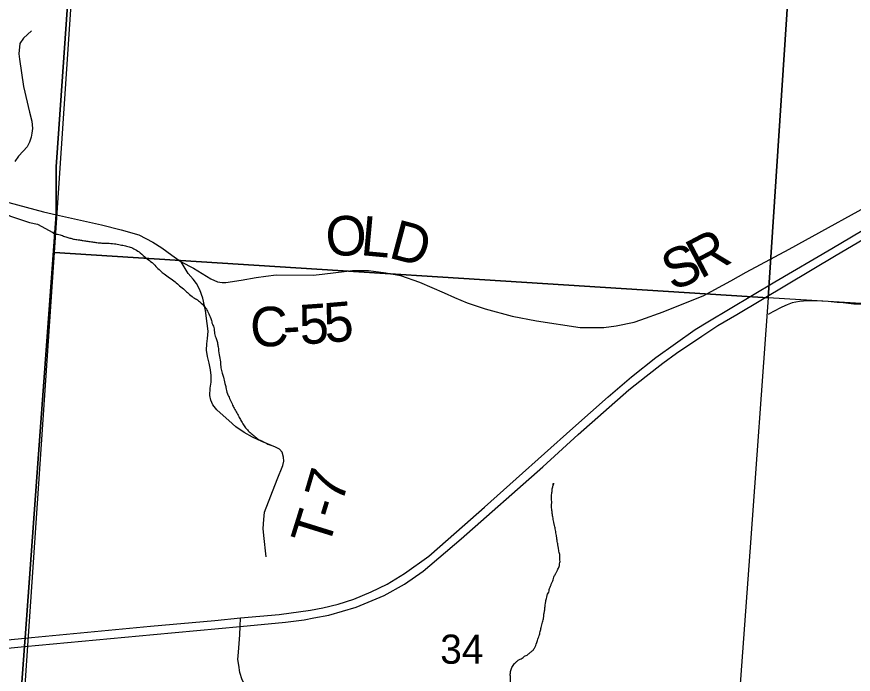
# Model space of a CAD drawing. Extents: x -13.7 to 34, y 0 to 32.3.
# Drawn here: x 25.84 to 27.041, y 18.512 to 19.456 of the extents above; entities that cross this region are included whole.
import ezdxf

# ---------------------------------------------------------------- set-up
doc = ezdxf.new("R2010")
doc.units = 0
for name, color, linetype in [('GM_X_Corporation', 7, 'Continuous'), ('GM_X_County_Road', 7, 'Continuous'), ('GM_X_County_Road_Text', 7, 'Continuous'), ('GM_X_Minor_River', 7, 'Continuous'), ('GM_X_Section_Text', 7, 'Continuous'), ('GM_X_State_Route', 7, 'Continuous'), ('GM_X_Township_Road', 7, 'Continuous'), ('GM_X_Township_Road_Text', 7, 'Continuous')]:
    doc.layers.add(name, color=color, linetype=linetype)

msp = doc.modelspace()

# ---------------------------------------------------------------- linework, layer by layer
at = {"layer": 'GM_X_Corporation'}
for points in [[(25.8396, 18.3951), (25.8512, 18.5523), (25.8521, 18.5644), (25.8715, 18.8281), (25.8969, 19.1723), (25.8969, 19.2407), (25.917, 19.5276), (25.9325, 19.8164), (25.9462, 20.0191), (25.9566, 20.1753), (25.9834, 20.5724), (26.0026, 20.9), (23.5167, 20.9)], [(25.8396, 18.3951), (25.8512, 18.5523), (25.8521, 18.5644), (25.8715, 18.8281), (25.8969, 19.1723), (25.8969, 19.2407), (25.917, 19.5276), (25.9325, 19.8164), (25.9462, 20.0191), (25.9566, 20.1753), (25.9834, 20.5724), (26.0026, 20.9), (23.5167, 20.9)], [(29.9598, 20.9), (26.0026, 20.9), (25.9834, 20.5724), (25.9566, 20.1753), (25.9462, 20.0191), (25.9325, 19.8164), (25.917, 19.5276), (25.8969, 19.2407), (25.8969, 19.1723), (25.8715, 18.8281), (25.8521, 18.5644), (25.8512, 18.5523), (25.8396, 18.3951), (25.8286, 18.2247), (25.8036, 17.8534), (25.7648, 17.1991), (25.7595, 17.1252), (25.7591, 17.1039), (25.7561, 17.0683), (25.752, 17.037), (25.7481, 16.9763), (25.7164, 16.6052), (25.6857, 16.1459), (25.6733, 15.948)], [(29.9598, 20.9), (26.0026, 20.9), (25.9834, 20.5724), (25.9566, 20.1753), (25.9462, 20.0191), (25.9325, 19.8164), (25.917, 19.5276), (25.8969, 19.2407), (25.8969, 19.1723), (25.8715, 18.8281), (25.8521, 18.5644), (25.8512, 18.5523), (25.8396, 18.3951), (25.8286, 18.2247), (25.8036, 17.8534), (25.7648, 17.1991), (25.7595, 17.1252), (25.7591, 17.1039), (25.7561, 17.0683), (25.752, 17.037), (25.7481, 16.9763), (25.7164, 16.6052), (25.6857, 16.1459), (25.6733, 15.948)]]:
    msp.add_lwpolyline(points, dxfattribs=at)
for points in [[(26.9853, 20.0635), (26.9188, 19.0522), (25.8944, 19.1175), (25.9617, 20.1223)], [(28.0076, 20.0028), (27.9343, 18.9903), (27.9295, 18.9907), (26.9188, 19.0522), (26.9853, 20.0635)], [(25.8944, 19.1175), (26.9188, 19.0522), (26.8924, 18.6876), (26.8578, 18.216), (26.8422, 18.014), (25.8244, 18.0867)]]:
    msp.add_lwpolyline(points, close=True, dxfattribs=at)
at = {"layer": 'GM_X_County_Road'}
for points in [[(26.7689, 19.0326), (26.8253, 19.0552), (26.8652, 19.0766), (26.8873, 19.0892), (26.9488, 19.1225), (27.0948, 19.2028), (27.131, 19.2223), (27.154, 19.2361), (27.1734, 19.251), (27.1897, 19.2652), (27.2083, 19.2853), (27.2189, 19.2978)], [(25.5601, 19.2293), (25.5694, 19.2351), (25.5787, 19.241), (25.588, 19.2455), (25.5949, 19.2484), (25.6041, 19.2507), (25.6133, 19.2529), (25.6204, 19.2536), (25.6267, 19.2533), (25.6352, 19.2529), (25.6443, 19.2506), (25.6601, 19.2469), (25.6874, 19.2366), (25.7171, 19.2254), (25.7512, 19.2127), (25.7646, 19.2078), (25.7783, 19.2026), (25.8785, 19.1759), (25.8971, 19.1718)], [(25.8971, 19.1718), (25.9616, 19.1573), (25.9898, 19.1502), (26.0152, 19.1427), (26.0353, 19.1324), (26.0482, 19.1244), (26.0628, 19.1137), (26.0762, 19.1042), (26.0938, 19.0949), (26.1187, 19.0799), (26.1285, 19.0755), (26.1348, 19.0744), (26.1403, 19.0743), (26.1625, 19.0777), (26.184, 19.0814), (26.1978, 19.0837), (26.2126, 19.0854), (26.2657, 19.0849), (26.2788, 19.0863), (26.2984, 19.0888), (26.3221, 19.0917), (26.3451, 19.0917), (26.3701, 19.0884), (26.3911, 19.0843), (26.4184, 19.0748), (26.4537, 19.0597), (26.4683, 19.0527), (26.4868, 19.0452), (26.5124, 19.0368), (26.5514, 19.0262), (26.5863, 19.0192), (26.6487, 19.0099), (26.6644, 19.0097), (26.6828, 19.0099), (26.7006, 19.0122), (26.7266, 19.0176), (26.7361, 19.0209), (26.7679, 19.0322), (26.7689, 19.0326)]]:
    msp.add_lwpolyline(points, dxfattribs=at)
at = {"layer": 'GM_X_Minor_River'}
msp.add_lwpolyline([(25.7155, 19.1142), (25.7257, 19.1244), (25.7386, 19.1282), (25.7488, 19.1369), (25.7548, 19.1483), (25.762, 19.1623), (25.7737, 19.1752), (25.7851, 19.1787), (25.8059, 19.1787), (25.8184, 19.1757), (25.8313, 19.1696), (25.8453, 19.1651), (25.8582, 19.1606), (25.87, 19.1583), (25.8921, 19.1463)], dxfattribs=at)
for points in [[(25.8921, 19.1471), (25.8921, 19.1463), (25.8988, 19.1438), (25.9056, 19.1417), (25.912, 19.1396), (25.9176, 19.1379), (25.9232, 19.1366), (25.93, 19.1356), (25.9357, 19.1346), (25.9421, 19.1336), (25.9489, 19.1327), (25.9553, 19.1317), (25.9625, 19.1311), (25.9701, 19.1308), (25.9803, 19.1301), (25.9887, 19.1287), (25.9962, 19.1269), (26.003, 19.1252), (26.0101, 19.1219), (26.0175, 19.1171), (26.026, 19.1096), (26.0323, 19.1048), (26.04, 19.0974), (26.0459, 19.0915), (26.0518, 19.0867), (26.0596, 19.0811), (26.0674, 19.0752), (26.074, 19.0696), (26.081, 19.0637), (26.0865, 19.0586), (26.0936, 19.053), (26.0995, 19.0494), (26.1051, 19.0447), (26.1113, 19.038), (26.1149, 19.0314), (26.1188, 19.0229), (26.1204, 19.0164), (26.1229, 19.0099), (26.1241, 19.0011), (26.1265, 18.9938), (26.1282, 18.9881), (26.1292, 18.9819), (26.1307, 18.9705), (26.1326, 18.9606), (26.1331, 18.9518), (26.1351, 18.9441), (26.1368, 18.9384), (26.1388, 18.9296), (26.1405, 18.9238), (26.1425, 18.9146), (26.1457, 18.9081), (26.1492, 18.9), (26.1521, 18.8938), (26.156, 18.8872), (26.1596, 18.8806), (26.1628, 18.8748), (26.1664, 18.8686), (26.1712, 18.8628), (26.1767, 18.8577), (26.1822, 18.8529), (26.1881, 18.8486), (26.1945, 18.8457), (26.2008, 18.8424), (26.2065, 18.8403)], [(26.541, 18.3977), (26.5415, 18.3999), (26.5427, 18.4022), (26.5451, 18.4044), (26.5467, 18.4085), (26.5479, 18.4107), (26.5484, 18.4142), (26.5487, 18.4221), (26.5484, 18.4248), (26.549, 18.4441), (26.5495, 18.4464), (26.5501, 18.4525), (26.5505, 18.4547), (26.551, 18.4578), (26.5516, 18.465), (26.5526, 18.4706), (26.5527, 18.4756), (26.5524, 18.4782), (26.5518, 18.482), (26.5516, 18.4862), (26.551, 18.4912), (26.55, 18.4969), (26.5493, 18.4992), (26.5488, 18.5046), (26.5489, 18.5076), (26.5486, 18.5106), (26.5487, 18.5133), (26.5491, 18.5159), (26.55, 18.5186), (26.5508, 18.5216), (26.5528, 18.5246), (26.5548, 18.5272), (26.5576, 18.5301), (26.5611, 18.5327), (26.5642, 18.5341), (26.5669, 18.5359), (26.57, 18.5384), (26.5727, 18.5395), (26.5766, 18.5428), (26.5801, 18.5453), (26.5833, 18.5494), (26.5866, 18.5573), (26.5878, 18.5603), (26.5899, 18.5674), (26.5908, 18.57), (26.5916, 18.5731), (26.593, 18.5791), (26.5947, 18.5866), (26.5965, 18.5934), (26.5966, 18.5957), (26.597, 18.5983), (26.5979, 18.6029), (26.5985, 18.6093), (26.5991, 18.6135), (26.5995, 18.6161), (26.6009, 18.6225), (26.6021, 18.6267), (26.6038, 18.63), (26.6046, 18.6334), (26.6071, 18.6402), (26.6088, 18.6443), (26.6101, 18.6477), (26.6113, 18.6514), (26.6134, 18.6559), (26.6154, 18.6596), (26.617, 18.663), (26.6182, 18.6653), (26.6191, 18.6683), (26.6195, 18.6705), (26.62, 18.6739), (26.6198, 18.6774), (26.6199, 18.6804), (26.6189, 18.6869), (26.6176, 18.6934), (26.6173, 18.6957), (26.6164, 18.7006), (26.6157, 18.7045), (26.6151, 18.7094), (26.6145, 18.7129), (26.6132, 18.7205), (26.6126, 18.7236), (26.6116, 18.7278), (26.6109, 18.7301), (26.6103, 18.7343), (26.609, 18.7412), (26.6084, 18.7469), (26.6078, 18.7511), (26.6081, 18.7602), (26.6078, 18.764), (26.6081, 18.7716), (26.6086, 18.7742), (26.6086, 18.7765), (26.61, 18.7833), (26.6105, 18.7863), (26.6104, 18.7833)]]:
    msp.add_spline(points, degree=3, dxfattribs=at)
at = {"layer": 'GM_X_State_Route'}
for points in [[(25.8523, 18.5638), (25.8615, 18.5647), (26.032, 18.5809), (26.1244, 18.589), (26.1614, 18.5929), (26.2169, 18.5976), (26.2619, 18.6037), (26.2796, 18.6073), (26.3015, 18.6127), (26.3241, 18.6198), (26.3489, 18.6304), (26.3721, 18.6413), (26.3969, 18.6564), (26.4316, 18.6813), (26.4715, 18.7165), (26.5114, 18.7518), (26.5569, 18.7927), (26.6382, 18.8652), (26.6892, 18.9102), (26.7228, 18.9391), (26.7577, 18.9668), (26.8139, 19.0071), (26.8322, 19.0181), (26.9284, 19.0755), (27.01, 19.1233), (27.1077, 19.1812)], [(25.8514, 18.5518), (26.0363, 18.5692), (26.1609, 18.5805), (26.226, 18.5865), (26.2529, 18.5899), (26.2667, 18.5928), (26.2882, 18.5966), (26.3274, 18.608), (26.3676, 18.6252), (26.3967, 18.6413), (26.4234, 18.6599), (26.4781, 18.7064), (26.5952, 18.8099), (26.6462, 18.856), (26.7189, 18.9201), (26.7435, 18.9401), (26.7676, 18.9584), (26.7872, 18.9731), (26.8234, 18.9975), (26.8466, 19.0127), (26.8737, 19.0286), (27.0165, 19.1136), (27.1115, 19.1698)], [(25.7758, 18.5564), (25.8523, 18.5638)], [(25.7749, 18.5443), (25.8514, 18.5518)]]:
    msp.add_lwpolyline(points, dxfattribs=at)
at = {"layer": 'GM_X_Township_Road'}
for points in [[(25.8615, 19.4357), (25.8497, 19.4255), (25.8446, 19.4177), (25.8432, 19.4029), (25.8442, 19.3949), (25.8499, 19.3558), (25.8586, 19.3188), (25.8618, 19.3062), (25.8627, 19.2957), (25.8618, 19.2891), (25.8609, 19.2832), (25.8584, 19.2761), (25.8549, 19.2694), (25.8493, 19.2629), (25.8426, 19.256), (25.8375, 19.2484)], [(26.1981, 18.6807), (26.1948, 18.7113), (26.1941, 18.721), (26.1946, 18.7343), (26.196, 18.7446), (26.2139, 18.7914), (26.2221, 18.8116), (26.2234, 18.8179), (26.223, 18.8237), (26.221, 18.8306), (26.2172, 18.8351), (26.2118, 18.8379), (26.1918, 18.8463), (26.1786, 18.8523), (26.1665, 18.859), (26.1545, 18.8674), (26.1444, 18.8762), (26.1366, 18.8833), (26.1272, 18.8917), (26.1214, 18.8986), (26.1186, 18.9057), (26.1173, 18.9124), (26.1179, 18.9225), (26.119, 18.9311), (26.1192, 18.9408), (26.1183, 18.9488), (26.1164, 18.9587), (26.114, 18.9683), (26.1125, 18.9772), (26.113, 18.9864), (26.114, 18.9942), (26.1151, 19.0045), (26.1136, 19.0157), (26.1112, 19.0342), (26.1072, 19.0521), (26.1031, 19.0641), (26.0981, 19.073), (26.0936, 19.079), (26.0863, 19.0874), (26.0762, 19.1042)], [(27.081, 19.0426), (27.0586, 19.0431), (27.0418, 19.0431), (27.0265, 19.0451), (27.0177, 19.0458), (27.0051, 19.0473), (26.9866, 19.048), (26.9753, 19.048), (26.9637, 19.0473), (26.9533, 19.0451), (26.9462, 19.0426), (26.9383, 19.0391), (26.9257, 19.0322), (26.9188, 19.0283)], [(26.31, 18.3291), (26.3049, 18.3394), (26.2963, 18.3571), (26.2883, 18.3718), (26.2819, 18.3807), (26.27, 18.3944), (26.2526, 18.4104), (26.2072, 18.4517), (26.1807, 18.4757), (26.1733, 18.4853), (26.1678, 18.4958), (26.1639, 18.5038), (26.1604, 18.5145), (26.159, 18.5251), (26.1577, 18.5331), (26.1583, 18.5436), (26.1603, 18.5686), (26.1609, 18.5805), (26.1614, 18.5929)]]:
    msp.add_lwpolyline(points, dxfattribs=at)

# ---------------------------------------------------------------- texts
at = {"layer": 'GM_X_County_Road_Text'}
for s, rotation, p in [('O', 1.9565, (26.2843, 19.1122)), ('L', 354.76, (26.3324, 19.1139)), ('D', 345.1014, (26.3723, 19.1105)), ('R', 27.8588, (26.8215, 19.0789)), ('S', 22.78, (26.7812, 19.0617)), ('5', 4.9574, (26.2834, 18.9877)), ('C', 3.077, (26.1766, 18.9813)), ('5', 4.016, (26.2475, 18.9852)), ('-', 3.3956, (26.2235, 18.9838))]:
    msp.add_text(s, height=0.0568, rotation=rotation, dxfattribs=at).set_placement(p)
at = {"layer": 'GM_X_Section_Text'}
msp.add_text('34', height=0.04186, rotation=0, dxfattribs=at).set_placement((26.448, 18.527))
at = {"layer": 'GM_X_Township_Road_Text'}
for s, rotation, p in [('7', 73.5821, (26.3069, 18.7554)), ('-', 72.8192, (26.2998, 18.7323)), ('T', 72.6879, (26.2871, 18.6916))]:
    msp.add_text(s, height=0.0568, rotation=rotation, dxfattribs=at).set_placement(p)

doc.saveas('drawing.dxf')
